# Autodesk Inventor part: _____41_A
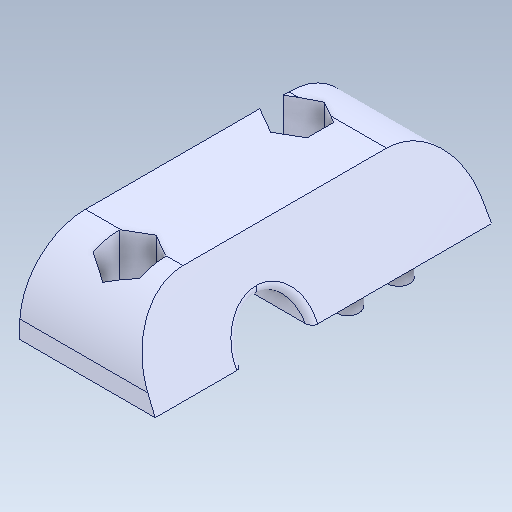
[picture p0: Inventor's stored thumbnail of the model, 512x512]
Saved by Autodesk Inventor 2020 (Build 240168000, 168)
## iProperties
Created: 2017-09
Part Number: _____41_A
Material: Générique
Document SubType Name: Modeling
Designer: bruno
Density: 1 g/cm^3
Appearance: Par défaut
Author: bruno
Sending System: SolidWorks 2016
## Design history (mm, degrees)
feature "Importée1"
node "Solide1"
